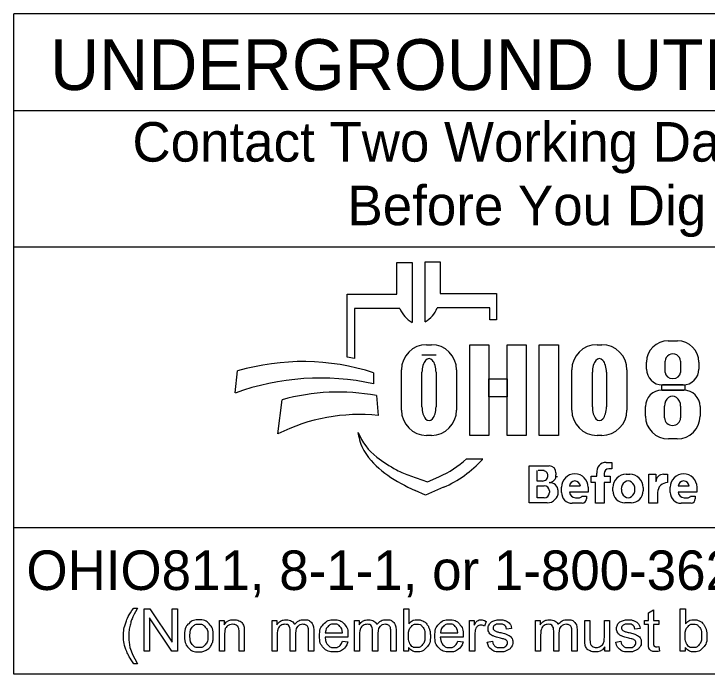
# Model space of a CAD drawing. Extents: x 0 to 34, y 0 to 22.
# Drawn here: x 2.378 to 4.831, y 2.934 to 5.272 of the extents above; entities that cross this region are included whole.
import ezdxf

# ---------------------------------------------------------------- set-up
doc = ezdxf.new("R2010")
doc.units = 0
doc.layers.add('SH_Data', color=7, linetype='Continuous')
doc.layers.add('SH_Text', color=7, linetype='Continuous')

msp = doc.modelspace()

# ---------------------------------------------------------------- linework, layer by layer
at = {"layer": 'SH_Data'}
for p, q in [((2.3775, 2.9345), (2.3775, 5.272)), ((6.6275, 5.272), (2.3775, 5.272)), ((2.3775, 4.9304), (6.6275, 4.9304)), ((2.3775, 4.447), (6.6275, 4.447)), ((6.6275, 3.4523), (2.3775, 3.4523)), ((6.6275, 2.9345), (2.3775, 2.9345))]:
    msp.add_line(p, q, dxfattribs=at)
at = {"layer": 'SH_Text'}
for p, q in [((3.8329, 4.1817), (3.8329, 4.3938)), ((3.8329, 4.3938), (3.8865, 4.3938)), ((3.8865, 4.3938), (3.8865, 4.2823)), ((3.7335, 4.28), (3.7335, 4.3915)), ((3.7335, 4.3915), (3.7872, 4.3915)), ((3.7872, 4.3915), (3.7872, 4.1794)), ((3.5576, 4.0561), (3.5576, 4.28)), ((3.5576, 4.28), (3.7335, 4.28)), ((3.8865, 4.2823), (4.0857, 4.2823)), ((4.0857, 4.2823), (4.0857, 4.1885)), ((3.5828, 4.2285), (3.5828, 4.0517)), ((3.7439, 4.2285), (3.5828, 4.2285)), ((4.0625, 4.2308), (3.8761, 4.2308)), ((4.0625, 4.1885), (4.0625, 4.2308)), ((4.0857, 4.1885), (4.0625, 4.1885)), ((3.8385, 4.1008), (3.8551, 4.1008)), ((4.4416, 4.1008), (4.4581, 4.1008)), ((4.6931, 4.1148), (4.7258, 4.1148)), ((3.8718, 4.0638), (3.822, 4.0638)), ((4.6168, 4.0142), (4.6168, 4.0385)), ((4.683, 4.0028), (4.683, 4.0421)), ((4.7371, 4.0421), (4.7371, 4.0028)), ((4.8022, 4.0385), (4.8022, 4.0142)), ((3.1602, 3.9298), (3.1696, 4.0079)), ((3.6509, 4.0014), (3.6509, 3.9626)), ((3.7491, 3.8693), (3.7491, 4.0113)), ((3.822, 3.8807), (3.822, 4.003)), ((3.8718, 4.003), (3.8718, 3.8807)), ((3.9445, 4.0113), (3.9445, 3.8693)), ((4.3521, 3.8693), (4.3521, 4.0113)), ((4.425, 3.8807), (4.425, 4.003)), ((4.4748, 4.003), (4.4748, 3.8807)), ((4.5476, 4.0113), (4.5476, 3.8693)), ((4.7462, 3.9582), (4.6728, 3.9582)), ((4.671, 3.9399), (4.7483, 3.9399)), ((3.312, 3.7852), (3.3267, 3.9054)), ((3.6608, 3.9208), (3.6671, 3.8498)), ((4.6131, 3.8479), (4.6131, 3.882)), ((4.6806, 3.842), (4.6806, 3.8829)), ((4.7374, 3.8829), (4.7374, 3.842)), ((4.8062, 3.882), (4.8062, 3.8479)), ((3.5997, 3.7723), (3.5967, 3.7903)), ((3.8551, 3.7798), (3.8385, 3.7798)), ((4.4581, 3.7798), (4.4416, 3.7798)), ((4.7252, 3.767), (4.6941, 3.767)), ((3.98, 3.6965), (4.0375, 3.6965)), ((4.4739, 3.6842), (4.4934, 3.6842)), ((4.4934, 3.6842), (4.4934, 3.6612)), ((4.2013, 3.5407), (4.2013, 3.6714)), ((4.2013, 3.6714), (4.2725, 3.6714)), ((4.4934, 3.6608), (4.4832, 3.6608)), ((3.7816, 3.6361), (3.841, 3.6156)), ((3.841, 3.6156), (3.8821, 3.6334)), ((4.2293, 3.618), (4.2293, 3.6549)), ((4.2545, 3.6549), (4.2332, 3.6549)), ((4.2963, 3.6477), (4.2963, 3.6398)), ((4.4213, 3.6129), (4.4213, 3.6358)), ((4.4213, 3.6358), (4.4406, 3.6358)), ((4.4406, 3.6358), (4.4406, 3.6463)), ((4.4667, 3.6443), (4.4667, 3.6358)), ((4.4667, 3.6358), (4.4883, 3.6358)), ((4.4883, 3.6358), (4.4883, 3.6129)), ((4.5451, 3.6424), (4.5573, 3.6424)), ((4.6254, 3.5395), (4.6254, 3.6422)), ((4.6254, 3.6422), (4.6499, 3.6422)), ((4.6499, 3.6422), (4.6499, 3.6153)), ((4.6772, 3.6422), (4.691, 3.6422)), ((4.691, 3.6422), (4.691, 3.6125)), ((4.2487, 3.618), (4.2293, 3.618)), ((4.4362, 3.6129), (4.4213, 3.6129)), ((4.4362, 3.5395), (4.4362, 3.6129)), ((4.4883, 3.6129), (4.4667, 3.6129)), ((4.4667, 3.6129), (4.4667, 3.5395)), ((3.835, 3.5686), (3.7976, 3.585)), ((3.8983, 3.596), (3.835, 3.5686)), ((4.2293, 3.5585), (4.2293, 3.6014)), ((4.2293, 3.6014), (4.2548, 3.6014)), ((4.2729, 3.5833), (4.2729, 3.5769)), ((4.3159, 3.5775), (4.3159, 3.5959)), ((4.3824, 3.5999), (4.3439, 3.5999)), ((4.4104, 3.5959), (4.4104, 3.5782)), ((4.4973, 3.5838), (4.4973, 3.5946)), ((4.6051, 3.5946), (4.6051, 3.5838)), ((4.7008, 3.5775), (4.7008, 3.5959)), ((4.7674, 3.5999), (4.7288, 3.5999)), ((4.7953, 3.5959), (4.7953, 3.5782)), ((4.2546, 3.5585), (4.2293, 3.5585)), ((4.3043, 3.5804), (4.3043, 3.58)), ((4.4104, 3.5782), (4.344, 3.5782)), ((4.3649, 3.559), (4.379, 3.559)), ((4.3876, 3.5646), (4.4045, 3.5646)), ((4.4045, 3.5646), (4.4045, 3.5547)), ((4.6559, 3.5776), (4.6559, 3.5395)), ((4.7953, 3.5782), (4.7289, 3.5782)), ((4.7498, 3.559), (4.7639, 3.559)), ((4.7725, 3.5646), (4.7894, 3.5646)), ((4.7894, 3.5646), (4.7894, 3.5547)), ((4.265, 3.5407), (4.2013, 3.5407)), ((4.3892, 3.5395), (4.3538, 3.5395)), ((4.4667, 3.5395), (4.4362, 3.5395)), ((4.5623, 3.541), (4.5401, 3.541)), ((4.6559, 3.5395), (4.6254, 3.5395)), ((4.7742, 3.5395), (4.7388, 3.5395))]:
    msp.add_line(p, q, dxfattribs=at)
for points in [[(3.991, 4.0997), (4.0589, 4.0997), (4.0589, 3.7798), (3.991, 3.7798)], [(4.1231, 4.0997), (4.1911, 4.0997), (4.1911, 3.7798), (4.1231, 3.7798)], [(4.2364, 4.0997), (4.3052, 4.0997), (4.3052, 3.7798), (4.2364, 3.7798)], [(4.0589, 3.9798), (4.1231, 3.9798), (4.1231, 3.9158), (4.0589, 3.9158)], [(4.6706, 3.9582), (4.7523, 3.9582), (4.7523, 3.9397), (4.6706, 3.9397)]]:
    msp.add_lwpolyline(points, close=True, dxfattribs=at)
for points in [[(2.8021, 3.1683), (2.8153, 3.1683)], [(2.8389, 3.0156), (2.8389, 3.1657), (2.8592, 3.1657), (2.9382, 3.0478), (2.9382, 3.1657), (2.9572, 3.1657), (2.9572, 3.0156), (2.9369, 3.0156), (2.8579, 3.1335), (2.8579, 3.0156), (2.8389, 3.0156)], [(3.7743, 3.0156), (3.7573, 3.0156), (3.7573, 3.1657), (3.7757, 3.1657), (3.7757, 3.1122)], [(4.7534, 3.0156), (4.7363, 3.0156), (4.7363, 3.1657), (4.7548, 3.1657), (4.7548, 3.1122)], [(4.6233, 3.0474), (4.6233, 3.1101), (4.6097, 3.1101), (4.6097, 3.1244), (4.6233, 3.1244), (4.6233, 3.1514), (4.6417, 3.1624), (4.6417, 3.1244), (4.6601, 3.1244), (4.6601, 3.1101), (4.6417, 3.1101), (4.6417, 3.0464)], [(3.1048, 3.0156), (3.1048, 3.1244), (3.1214, 3.1244), (3.1214, 3.109)], [(3.2912, 3.0156), (3.2912, 3.1244), (3.3077, 3.1244), (3.3077, 3.1091)], [(3.5826, 3.0156), (3.5826, 3.1244), (3.5991, 3.1244), (3.5991, 3.1091)], [(3.9904, 3.0156), (3.9904, 3.1244), (4.007, 3.1244), (4.007, 3.1079)], [(4.0495, 3.1209), (4.043, 3.1039)], [(4.2236, 3.0156), (4.2236, 3.1244), (4.2401, 3.1244), (4.2401, 3.1091)], [(4.3979, 3.057), (4.3979, 3.1244), (4.4164, 3.1244), (4.4164, 3.0641)], [(4.4676, 3.0662), (4.4676, 3.1244), (4.4861, 3.1244), (4.4861, 3.0156), (4.4696, 3.0156)], [(4.1394, 3.0963), (4.1213, 3.0939)], [(4.594, 3.0963), (4.5759, 3.0939)], [(3.1233, 3.075), (3.1233, 3.0156), (3.1048, 3.0156)], [(3.1932, 3.0825), (3.1932, 3.0156), (3.1748, 3.0156), (3.1748, 3.0817)], [(3.3097, 3.072), (3.3097, 3.0156), (3.2912, 3.0156)], [(3.3743, 3.0788), (3.3743, 3.0156), (3.3559, 3.0156), (3.3559, 3.0862)], [(3.4388, 3.0903), (3.4388, 3.0156), (3.4203, 3.0156), (3.4203, 3.0841)], [(3.4799, 3.0804), (3.5406, 3.0804)], [(3.601, 3.072), (3.601, 3.0156), (3.5826, 3.0156)], [(3.6657, 3.0788), (3.6657, 3.0156), (3.6473, 3.0156), (3.6473, 3.0862)], [(3.7301, 3.0903), (3.7301, 3.0156), (3.7117, 3.0156), (3.7117, 3.0841)], [(3.8879, 3.0804), (3.9486, 3.0804)], [(4.0088, 3.0726), (4.0088, 3.0156), (3.9904, 3.0156)], [(4.242, 3.072), (4.242, 3.0156), (4.2236, 3.0156)], [(4.3067, 3.0788), (4.3067, 3.0156), (4.2883, 3.0156), (4.2883, 3.0862)], [(4.3711, 3.0903), (4.3711, 3.0156), (4.3527, 3.0156), (4.3527, 3.0841)], [(3.56, 3.0653), (3.4788, 3.0653)], [(3.5404, 3.0507), (3.5595, 3.0483)], [(3.968, 3.0653), (3.8868, 3.0653)], [(3.9484, 3.0507), (3.9675, 3.0483)], [(4.053, 3.0481), (4.0712, 3.0509)], [(4.5076, 3.0481), (4.5258, 3.0509)], [(3.7743, 3.0292), (3.7743, 3.0156)], [(4.4696, 3.0156), (4.4696, 3.0317)], [(4.6601, 3.032), (4.6628, 3.0157)], [(4.7534, 3.0292), (4.7534, 3.0156)], [(2.8153, 2.9714), (2.8021, 2.9714)]]:
    msp.add_lwpolyline(points, dxfattribs=at)
for centre, radius, start, end in [((3.8353, 4.2653), 0.0985, 201.9296, 240.7469), ((3.7847, 4.2676), 0.0985, 299.2531, 338.0704), ((3.8385, 4.0113), 0.0895, 90, 180), ((3.8551, 4.0113), 0.0895, 0, 90), ((4.4416, 4.0113), 0.0895, 90, 180), ((4.4581, 4.0113), 0.0895, 0, 90), ((4.6931, 4.0385), 0.0763, 90, 180), ((4.7258, 4.0385), 0.0763, 0, 90), ((3.4295, 3.2471), 0.8191, 79.2074, 81.0007), ((3.3997, 3.2218), 0.8191, 72.1402, 106.3144), ((4.6728, 4.0142), 0.056, 180, 270), ((4.7462, 4.0142), 0.056, 270, 0), ((3.4628, 3.0907), 0.8919, 77.8238, 109.8274), ((3.5267, 3.201), 0.7322, 79.44, 105.8467), ((4.671, 3.882), 0.0579, 90, 180), ((4.7483, 3.882), 0.0579, 0, 90), ((3.5987, 3.2178), 0.6357, 83.8248, 116.8021), ((3.8385, 3.8693), 0.0895, 180, 270), ((3.8551, 3.8693), 0.0895, 270, 0), ((4.4416, 3.8693), 0.0895, 180, 270), ((4.4581, 3.8693), 0.0895, 270, 0), ((4.6941, 3.8479), 0.081, 180, 270), ((4.7252, 3.8479), 0.081, 270, 0), ((3.7841, 3.8624), 0.2008, 201.0457, 232.5314), ((3.741, 3.7964), 0.1433, 189.6817, 216.0884), ((3.8747, 3.8939), 0.3088, 216.0884, 235.7167), ((3.9766, 4.1136), 0.5173, 232.5314, 241.794), ((3.7387, 3.9639), 0.3602, 293.4582, 312.0712), ((3.7387, 3.9639), 0.401, 293.4582, 317.8286), ((4.4739, 3.6507), 0.0335, 90, 187.5187), ((3.8914, 3.9548), 0.3371, 241.794, 250.9821), ((4.2725, 3.6477), 0.0238, 0, 90), ((4.4832, 3.6443), 0.0165, 90, 180), ((4.0412, 4.1381), 0.6044, 235.7167, 246.2325), ((4.2487, 3.6367), 0.0187, 270, 2.0582), ((4.2505, 3.638), 0.0169, 357.8325, 90), ((4.2721, 3.637), 0.0243, 270, 6.6529), ((4.2827, 3.6355), 0.0175, 347.4023, 0), ((4.3631, 3.5959), 0.0473, 0, 180), ((4.5451, 3.5946), 0.0478, 90, 180), ((4.5573, 3.5946), 0.0478, 0, 90), ((4.6768, 3.6153), 0.0269, 89.2449, 180), ((4.7481, 3.5959), 0.0473, 0, 180), ((4.2722, 3.5806), 0.0321, 4.0748, 90), ((4.3632, 3.5989), 0.0193, 2.9632, 177.0368), ((4.6908, 3.5776), 0.0349, 89.6033, 180), ((4.7481, 3.5989), 0.0193, 2.9632, 177.0368), ((4.2548, 3.5833), 0.0181, 0, 90), ((4.2714, 3.5804), 0.033, 0, 11.7502), ((4.5401, 3.5838), 0.0428, 180, 270), ((4.5623, 3.5838), 0.0428, 270, 0), ((4.2546, 3.5769), 0.0184, 270, 0), ((4.265, 3.58), 0.0393, 270, 0), ((4.3538, 3.5775), 0.038, 180, 270), ((4.3649, 3.58), 0.021, 184.827, 270), ((4.379, 3.5684), 0.00938, 270, 335.9979), ((4.7388, 3.5775), 0.038, 180, 270), ((4.7498, 3.58), 0.021, 184.827, 270), ((4.7639, 3.5684), 0.00938, 270, 335.9979), ((4.3892, 3.5547), 0.0152, 270, 0), ((4.7742, 3.5547), 0.0152, 270, 0)]:
    msp.add_arc(centre, radius, start, end, dxfattribs=at)
for centre, major_axis, ratio, start_param, end_param in [((3.8469, 4.003), (0, 0.0484), 0.514403, 4.712389, 7.853982), ((4.4499, 4.003), (0, 0.0484), 0.514403, 4.712389, 7.853982), ((4.71, 4.0421), (0.0271, 0), 0.969373, 0, 3.141593), ((4.71, 4.0028), (0.0271, 0), 0.818453, 3.141593, 6.283185), ((4.709, 3.8829), (0, 0.0358), 0.794529, 4.712389, 7.853982), ((3.8469, 3.8807), (0, 0.0484), 0.514403, 1.570796, 4.712389), ((4.4499, 3.8807), (0, 0.0484), 0.514403, 1.570796, 4.712389), ((4.709, 3.842), (0.0284, 0), 0.959837, 3.141593, 6.283185), ((4.5517, 3.5892), (0, 0.029), 0.832186, 4.712389, 7.853982), ((4.5517, 3.5892), (0, 0.0302), 0.797287, 1.570796, 4.712389)]:
    msp.add_ellipse(centre, major_axis=major_axis, ratio=ratio, start_param=start_param, end_param=end_param, dxfattribs=at)
for points in [[(2.8021, 2.9714), (2.7869, 2.9907), (2.7763, 3.0165), (2.7657, 3.0423), (2.7657, 3.0699), (2.7657, 3.0943), (2.7736, 3.1166), (2.7829, 3.1425), (2.8021, 3.1683)], [(2.8153, 3.1683), (2.8029, 3.147), (2.7989, 3.1378), (2.7927, 3.1237), (2.7891, 3.1083), (2.7847, 3.0892), (2.7847, 3.0698), (2.7847, 3.0206), (2.8153, 2.9714)], [(2.9814, 3.07), (2.9814, 3.1002), (2.9981, 3.1147), (3.0122, 3.1268), (3.0323, 3.1268), (3.0547, 3.1268), (3.069, 3.1121), (3.0832, 3.0974), (3.0832, 3.0715), (3.0832, 3.0506), (3.0769, 3.0385), (3.0706, 3.0265), (3.0586, 3.0198), (3.0466, 3.0132), (3.0323, 3.0132), (3.0095, 3.0132), (2.9954, 3.0278), (2.9814, 3.0425), (2.9814, 3.07)], [(3.1214, 3.109), (3.1334, 3.1268), (3.156, 3.1268), (3.1659, 3.1268), (3.1741, 3.1233), (3.1823, 3.1198), (3.1864, 3.114), (3.1905, 3.1083), (3.1922, 3.1004), (3.1932, 3.0953), (3.1932, 3.0825)], [(3.3077, 3.1091), (3.3128, 3.1171), (3.3214, 3.1219), (3.3299, 3.1268), (3.3407, 3.1268), (3.3528, 3.1268), (3.3606, 3.1218), (3.3683, 3.1168), (3.3715, 3.1077), (3.3844, 3.1268), (3.4051, 3.1268), (3.4213, 3.1268), (3.43, 3.1179), (3.4388, 3.1089), (3.4388, 3.0903)], [(3.5595, 3.0483), (3.555, 3.0316), (3.5428, 3.0224), (3.5306, 3.0132), (3.5117, 3.0132), (3.4878, 3.0132), (3.4738, 3.0279), (3.4598, 3.0426), (3.4598, 3.0691), (3.4598, 3.0965), (3.474, 3.1117), (3.4881, 3.1268), (3.5106, 3.1268), (3.5324, 3.1268), (3.5463, 3.112), (3.5601, 3.0971), (3.5601, 3.0702), (3.5601, 3.0685), (3.56, 3.0653)], [(3.5991, 3.1091), (3.6042, 3.1171), (3.6127, 3.1219), (3.6212, 3.1268), (3.6321, 3.1268), (3.6442, 3.1268), (3.6519, 3.1218), (3.6597, 3.1168), (3.6628, 3.1077), (3.6758, 3.1268), (3.6965, 3.1268), (3.7127, 3.1268), (3.7214, 3.1179), (3.7301, 3.1089), (3.7301, 3.0903)], [(3.7757, 3.1122), (3.7874, 3.1268), (3.8055, 3.1268), (3.8155, 3.1268), (3.8245, 3.1228), (3.8335, 3.1187), (3.8392, 3.1114), (3.845, 3.1041), (3.8483, 3.0938), (3.8516, 3.0834), (3.8516, 3.0716), (3.8516, 3.0437), (3.8378, 3.0284), (3.8239, 3.0132), (3.8046, 3.0132), (3.7853, 3.0132), (3.7743, 3.0292)], [(3.9675, 3.0483), (3.963, 3.0316), (3.9508, 3.0224), (3.9386, 3.0132), (3.9196, 3.0132), (3.8958, 3.0132), (3.8818, 3.0279), (3.8678, 3.0426), (3.8678, 3.0691), (3.8678, 3.0965), (3.882, 3.1117), (3.8961, 3.1268), (3.9186, 3.1268), (3.9404, 3.1268), (3.9543, 3.112), (3.9681, 3.0971), (3.9681, 3.0702), (3.9681, 3.0685), (3.968, 3.0653)], [(4.007, 3.1079), (4.0133, 3.1195), (4.0187, 3.1231), (4.0241, 3.1268), (4.0305, 3.1268), (4.0398, 3.1268), (4.0495, 3.1209)], [(4.0712, 3.0509), (4.0727, 3.04), (4.0798, 3.0341), (4.0868, 3.0283), (4.0995, 3.0283), (4.1122, 3.0283), (4.1184, 3.0335), (4.1245, 3.0387), (4.1245, 3.0456), (4.1245, 3.0519), (4.1191, 3.0555), (4.1153, 3.0579), (4.1002, 3.0617), (4.0799, 3.0669), (4.072, 3.0706), (4.0642, 3.0743), (4.0601, 3.0809), (4.0561, 3.0875), (4.0561, 3.0955), (4.0561, 3.1028), (4.0594, 3.109), (4.0628, 3.1152), (4.0685, 3.1193), (4.0728, 3.1224), (4.0803, 3.1246), (4.0877, 3.1268), (4.0962, 3.1268), (4.109, 3.1268), (4.1187, 3.1231), (4.1284, 3.1194), (4.133, 3.1131), (4.1377, 3.1068), (4.1394, 3.0963)], [(4.2401, 3.1091), (4.2452, 3.1171), (4.2537, 3.1219), (4.2622, 3.1268), (4.2731, 3.1268), (4.2852, 3.1268), (4.2929, 3.1218), (4.3007, 3.1168), (4.3038, 3.1077), (4.3168, 3.1268), (4.3375, 3.1268), (4.3537, 3.1268), (4.3624, 3.1179), (4.3711, 3.1089), (4.3711, 3.0903)], [(4.5258, 3.0509), (4.5273, 3.04), (4.5343, 3.0341), (4.5414, 3.0283), (4.554, 3.0283), (4.5668, 3.0283), (4.5729, 3.0335), (4.5791, 3.0387), (4.5791, 3.0456), (4.5791, 3.0519), (4.5736, 3.0555), (4.5698, 3.0579), (4.5548, 3.0617), (4.5345, 3.0669), (4.5266, 3.0706), (4.5188, 3.0743), (4.5147, 3.0809), (4.5107, 3.0875), (4.5107, 3.0955), (4.5107, 3.1028), (4.514, 3.109), (4.5173, 3.1152), (4.5231, 3.1193), (4.5274, 3.1224), (4.5348, 3.1246), (4.5423, 3.1268), (4.5508, 3.1268), (4.5636, 3.1268), (4.5733, 3.1231), (4.583, 3.1194), (4.5876, 3.1131), (4.5922, 3.1068), (4.594, 3.0963)], [(4.7548, 3.1122), (4.7664, 3.1268), (4.7846, 3.1268), (4.7946, 3.1268), (4.8036, 3.1228), (4.8125, 3.1187), (4.8183, 3.1114), (4.8241, 3.1041), (4.8274, 3.0938), (4.8306, 3.0834), (4.8306, 3.0716), (4.8306, 3.0437), (4.8168, 3.0284), (4.803, 3.0132), (4.7836, 3.0132), (4.7644, 3.0132), (4.7534, 3.0292)], [(3.0003, 3.07), (3.0003, 3.0491), (3.0094, 3.0387), (3.0185, 3.0283), (3.0323, 3.0283), (3.046, 3.0283), (3.0551, 3.0387), (3.0642, 3.0492), (3.0642, 3.0706), (3.0642, 3.0908), (3.0551, 3.1012), (3.0459, 3.1116), (3.0323, 3.1116), (3.0185, 3.1116), (3.0094, 3.1013), (3.0003, 3.0909), (3.0003, 3.07)], [(3.1748, 3.0817), (3.1748, 3.093), (3.1726, 3.0986), (3.1705, 3.1041), (3.165, 3.1075), (3.1595, 3.1108), (3.1521, 3.1108), (3.1404, 3.1108), (3.1318, 3.1033), (3.1233, 3.0959), (3.1233, 3.075)], [(3.3559, 3.0862), (3.3559, 3.0985), (3.3514, 3.1047), (3.3469, 3.1108), (3.3366, 3.1108), (3.3288, 3.1108), (3.3222, 3.1067), (3.3156, 3.1026), (3.3126, 3.0947), (3.3097, 3.0868), (3.3097, 3.072)], [(3.4203, 3.0841), (3.4203, 3.0951), (3.4185, 3.1), (3.4168, 3.1049), (3.412, 3.1078), (3.4073, 3.1108), (3.401, 3.1108), (3.3895, 3.1108), (3.3819, 3.1032), (3.3743, 3.0955), (3.3743, 3.0788)], [(3.5406, 3.0804), (3.5394, 3.0941), (3.5337, 3.101), (3.5249, 3.1117), (3.5108, 3.1117), (3.4981, 3.1117), (3.4894, 3.1032), (3.4808, 3.0947), (3.4799, 3.0804)], [(3.6473, 3.0862), (3.6473, 3.0985), (3.6428, 3.1047), (3.6383, 3.1108), (3.628, 3.1108), (3.6202, 3.1108), (3.6136, 3.1067), (3.607, 3.1026), (3.604, 3.0947), (3.601, 3.0868), (3.601, 3.072)], [(3.7117, 3.0841), (3.7117, 3.0951), (3.7099, 3.1), (3.7081, 3.1049), (3.7034, 3.1078), (3.6987, 3.1108), (3.6923, 3.1108), (3.6809, 3.1108), (3.6733, 3.1032), (3.6657, 3.0955), (3.6657, 3.0788)], [(3.7741, 3.0708), (3.7741, 3.0512), (3.7794, 3.0425), (3.7881, 3.0283), (3.8029, 3.0283), (3.815, 3.0283), (3.8238, 3.0388), (3.8326, 3.0493), (3.8326, 3.0701), (3.8326, 3.0914), (3.8241, 3.1016), (3.8157, 3.1117), (3.8038, 3.1117), (3.7917, 3.1117), (3.7829, 3.1012), (3.7741, 3.0907), (3.7741, 3.0708)], [(3.9486, 3.0804), (3.9474, 3.0941), (3.9417, 3.101), (3.9328, 3.1117), (3.9188, 3.1117), (3.9061, 3.1117), (3.8974, 3.1032), (3.8888, 3.0947), (3.8879, 3.0804)], [(4.043, 3.1039), (4.0363, 3.1078), (4.0295, 3.1078), (4.0235, 3.1078), (4.0187, 3.1042), (4.0139, 3.1006), (4.0119, 3.0941), (4.0088, 3.0843), (4.0088, 3.0726)], [(4.1213, 3.0939), (4.1201, 3.1023), (4.1142, 3.107), (4.1083, 3.1117), (4.0975, 3.1117), (4.0848, 3.1117), (4.0794, 3.1075), (4.0739, 3.1033), (4.0739, 3.0977), (4.0739, 3.0941), (4.0762, 3.0912), (4.0785, 3.0882), (4.0833, 3.0863), (4.086, 3.0852), (4.0996, 3.0816), (4.1192, 3.0763), (4.1269, 3.073), (4.1347, 3.0697), (4.1391, 3.0633), (4.1435, 3.057), (4.1435, 3.0476), (4.1435, 3.0384), (4.1381, 3.0302), (4.1327, 3.0221), (4.1226, 3.0176), (4.1124, 3.0132), (4.0996, 3.0132), (4.0784, 3.0132), (4.0672, 3.022), (4.0561, 3.0308), (4.053, 3.0481)], [(4.2883, 3.0862), (4.2883, 3.0985), (4.2838, 3.1047), (4.2793, 3.1108), (4.269, 3.1108), (4.2612, 3.1108), (4.2546, 3.1067), (4.248, 3.1026), (4.245, 3.0947), (4.242, 3.0868), (4.242, 3.072)], [(4.3527, 3.0841), (4.3527, 3.0951), (4.3509, 3.1), (4.3491, 3.1049), (4.3444, 3.1078), (4.3397, 3.1108), (4.3333, 3.1108), (4.3219, 3.1108), (4.3143, 3.1032), (4.3067, 3.0955), (4.3067, 3.0788)], [(4.5759, 3.0939), (4.5747, 3.1023), (4.5688, 3.107), (4.5629, 3.1117), (4.5521, 3.1117), (4.5394, 3.1117), (4.5339, 3.1075), (4.5285, 3.1033), (4.5285, 3.0977), (4.5285, 3.0941), (4.5308, 3.0912), (4.533, 3.0882), (4.5378, 3.0863), (4.5406, 3.0852), (4.5542, 3.0816), (4.5737, 3.0763), (4.5815, 3.073), (4.5893, 3.0697), (4.5937, 3.0633), (4.5981, 3.057), (4.5981, 3.0476), (4.5981, 3.0384), (4.5927, 3.0302), (4.5873, 3.0221), (4.5772, 3.0176), (4.567, 3.0132), (4.5542, 3.0132), (4.5329, 3.0132), (4.5218, 3.022), (4.5107, 3.0308), (4.5076, 3.0481)], [(4.7532, 3.0708), (4.7532, 3.0512), (4.7585, 3.0425), (4.7672, 3.0283), (4.782, 3.0283), (4.7941, 3.0283), (4.8029, 3.0388), (4.8116, 3.0493), (4.8116, 3.0701), (4.8116, 3.0914), (4.8032, 3.1016), (4.7948, 3.1117), (4.7828, 3.1117), (4.7708, 3.1117), (4.762, 3.1012), (4.7532, 3.0907), (4.7532, 3.0708)], [(3.4788, 3.0653), (3.4799, 3.0473), (3.489, 3.0378), (3.4981, 3.0283), (3.5117, 3.0283), (3.5219, 3.0283), (3.5291, 3.0336), (3.5362, 3.039), (3.5404, 3.0507)], [(3.8868, 3.0653), (3.8879, 3.0473), (3.897, 3.0378), (3.9061, 3.0283), (3.9197, 3.0283), (3.9299, 3.0283), (3.937, 3.0336), (3.9442, 3.039), (3.9484, 3.0507)], [(4.4696, 3.0317), (4.4569, 3.0132), (4.4351, 3.0132), (4.4255, 3.0132), (4.4171, 3.0169), (4.4088, 3.0206), (4.4047, 3.0261), (4.4007, 3.0317), (4.3991, 3.0398), (4.3979, 3.0452), (4.3979, 3.057)], [(4.4164, 3.0641), (4.4164, 3.0497), (4.4175, 3.0447), (4.4192, 3.0374), (4.4249, 3.0332), (4.4305, 3.0291), (4.4388, 3.0291), (4.4471, 3.0291), (4.4543, 3.0333), (4.4616, 3.0376), (4.4646, 3.0449), (4.4676, 3.0522), (4.4676, 3.0662)], [(4.6628, 3.0157), (4.655, 3.0141), (4.6488, 3.0141), (4.6388, 3.0141), (4.6333, 3.0173), (4.6278, 3.0205), (4.6255, 3.0256), (4.6233, 3.0308), (4.6233, 3.0474)], [(4.6417, 3.0464), (4.6417, 3.0385), (4.6427, 3.0362), (4.6436, 3.0339), (4.6458, 3.0326), (4.648, 3.0313), (4.6521, 3.0313), (4.6551, 3.0313), (4.6601, 3.032)]]:
    msp.add_open_spline(points, degree=3, dxfattribs=at)

# ---------------------------------------------------------------- texts
for s, height, p in [('UNDERGROUND UTILITIES', 0.18, (2.5057, 5.0023)), ('Contact Two Working Days', 0.14, (2.7972, 4.7488)), ('Before You Dig', 0.14, (3.5583, 4.5238)), ('OHIO811, 8-1-1, or 1-800-362-2764', 0.14, (2.422, 3.2323))]:
    msp.add_text(s, height=height, dxfattribs=at).set_placement(p)

doc.saveas('drawing.dxf')
